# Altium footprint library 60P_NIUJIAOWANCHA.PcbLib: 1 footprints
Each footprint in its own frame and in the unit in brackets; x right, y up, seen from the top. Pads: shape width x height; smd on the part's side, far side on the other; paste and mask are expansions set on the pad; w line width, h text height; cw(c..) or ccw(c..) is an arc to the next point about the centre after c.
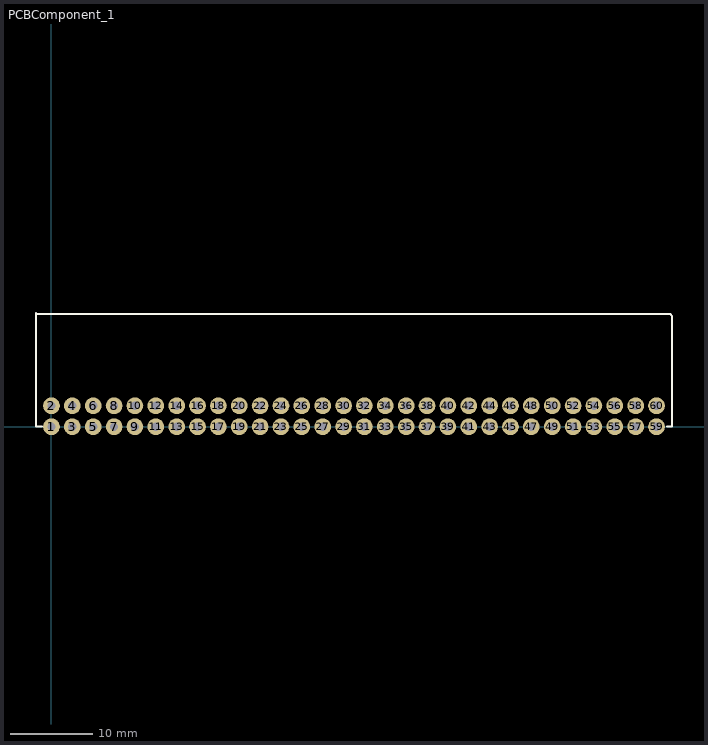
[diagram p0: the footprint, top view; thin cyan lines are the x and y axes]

## PCBComponent_1 [mm]
pads (60):
  round 2.04 hole 1.02: 1(0,0) 2(0,2.54) 3(2.54,0) 4(2.54,2.54) 5(5.08,0) 6(5.08,2.54) 7(7.62,0) 8(7.62,2.54) 9(10.16,0) 10(10.16,2.54) 11(12.7,0) 12(12.7,2.54) 13(15.24,0) 14(15.24,2.54) 15(17.78,0) 16(17.78,2.54) 17(20.32,0) 18(20.32,2.54) 19(22.86,0) 20(22.86,2.54) 21(25.4,0) 22(25.4,2.54) 23(27.94,0) 24(27.94,2.54) 25(30.48,0) 26(30.48,2.54) 27(33.02,0) 28(33.02,2.54) 29(35.56,0) 30(35.56,2.54) 31(38.1,0) 32(38.1,2.54) 33(40.64,0) 34(40.64,2.54) 35(43.18,0) 36(43.18,2.54) 37(45.72,0) 38(45.72,2.54) 39(48.26,0) 40(48.26,2.54) 41(50.8,0) 42(50.8,2.54) 43(53.34,0) 44(53.34,2.54) 45(55.88,0) 46(55.88,2.54) 47(58.42,0) 48(58.42,2.54) 49(60.96,0) 50(60.96,2.54) 51(63.5,0) 52(63.5,2.54) 53(66.04,0) 54(66.04,2.54) 55(68.58,0) 56(68.58,2.54) 57(71.12,0) 58(71.12,2.54) 59(73.66,0) 60(73.66,2.54)
Top Overlay:
  lines w0.254: -1.143,0 -1.905,0 -1.905,13.843 -1.778,13.716 75.311,13.716 75.565,13.462 75.565,0 74.93,0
